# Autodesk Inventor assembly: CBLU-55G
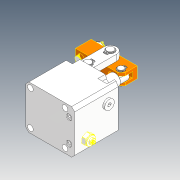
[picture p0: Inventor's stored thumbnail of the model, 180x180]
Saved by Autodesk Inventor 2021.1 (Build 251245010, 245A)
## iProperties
Created: 2019-05
Part Number: CBLU-55G
Description: STEP AP214
Document SubType Name: Assembly
Designer: user
Title: CBLU-55G.STEP
Revision Number: ÈÎºÎ
Sending System: SolidWorks 2016
Preprocessor: SwSTEP 2.0
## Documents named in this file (13)
- D:\Vault_2016\Projekty\Clamptek\Hydraulic\CBLU\CBLU-55\Inventor\CBLU-55G\CBLU-55G.iam
- D:\Vault_2016\Projekty\Clamptek\Hydraulic\CBLU\CBLU-55\Inventor\CBLU-55G\CBLU-55C±¾Ìå_1_1.ipt
- D:\Vault_2016\Projekty\Clamptek\Hydraulic\CBLU\CBLU-55\Inventor\CBLU-55G\changxiao.ipt
- D:\Vault_2016\Projekty\Clamptek\Hydraulic\CBLU\CBLU-55\Inventor\CBLU-55G\duanxiao.ipt
- D:\Vault_2016\Projekty\Clamptek\Hydraulic\CBLU\CBLU-55\Inventor\CBLU-55G\huosaigan_2_1.ipt
- D:\Vault_2016\Projekty\Clamptek\Hydraulic\CBLU\CBLU-55\Inventor\CBLU-55G\liangan.ipt
- D:\Vault_2016\Projekty\Clamptek\Hydraulic\CBLU\CBLU-55\Inventor\CBLU-55G\yabi.ipt
- D:\Vault_2016\Projekty\Clamptek\Hydraulic\CBLU\CBLU-55\Inventor\CBLU-55G\kahuang.ipt
- D:\Vault_2016\Projekty\Clamptek\Hydraulic\CBLU\CBLU-55\Inventor\CBLU-55G\kahuang01.ipt
- D:\Vault_2016\Projekty\Clamptek\Hydraulic\CBLU\CBLU-55\Inventor\CBLU-55G\luogan.ipt
- D:\Vault_2016\Projekty\Clamptek\Hydraulic\CBLU\CBLU-55\Inventor\CBLU-55G\luomu.ipt
- D:\Vault_2016\Projekty\Clamptek\Hydraulic\CBLU\CBLU-55\Inventor\CBLU-55G\ÄÚÁù½Ç¶ÂÍ·×îÐÂ1-4_1.ipt
- D:\Vault_2016\Projekty\Clamptek\Hydraulic\CBLU\CBLU-55\Inventor\CBLU-55G\CZL20µ÷ËÙ·§_1_1_1.ipt
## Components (18 placed, 18 different names)
1. CBLU-55C±¾Ìå_1_1_1
2. changxiao_2
3. duanxiao_3
4. huosaigan_2_1_4
5. liangan_5
6. yabi_6
7. liangan_7
8. changxiao_8
9. kahuang_9
10. kahuang_10
11. kahuang_11
12. kahuang_12
13. kahuang01_13
14. kahuang01_14
15. luogan_15
16. luomu_16
17. ÄÚÁù½Ç¶ÂÍ·×îÐÂ1-4_1_17
18. CZL20µ÷ËÙ·§_1_1_1_18
